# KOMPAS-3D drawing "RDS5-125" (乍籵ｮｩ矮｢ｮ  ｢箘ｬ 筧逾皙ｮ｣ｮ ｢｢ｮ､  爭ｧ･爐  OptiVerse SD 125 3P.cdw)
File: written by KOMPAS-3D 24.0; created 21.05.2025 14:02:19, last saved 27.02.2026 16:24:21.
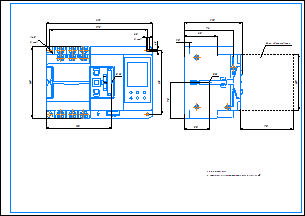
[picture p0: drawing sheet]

Document properties: Утвердил: Строгонов; Автор: keaz-admin; Проверил: Дорошев; Форматы листов документа: A2; Полное имя файла: D:\Проекты\OptiVerse SD\OptiVerse SD\OptiVerse SD 125 3P\КД\ГЖИК.648446.002ГЧ Устройство автоматического ввода резерва OptiVerse SD 125 3P (без рамки).cdw; Масса: 3.4; Т. контр.: Пашков А.Е.; Наименование: Устройство автоматического ввода резерва OptiVerse SD 125 3P / Габаритный чертеж; Н. контр.: Гаврикова; Количество листов документа: 1; Разработал: Сулейманова

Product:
- Body: Тело 4
    Масса: 0.000009
- Body: Тело 3
    Масса: 0.000001
- Component [assembly]: RDS5-125.STEP  | qty 1  | pos. 1  | Масса: 15.228655; source file: ..\3D\Сборка OptiVerse SD 125 3P.a3d
- Body: Тело 2
    Масса: 0.000056
- Part/product: RDS5-125
    Масса: 15.22872
    Форматы листов документа: A2

Views: Проекционный вид 2
Referenced files in D:\Проекты\OptiVerse SD\OptiVerse SD\OptiVerse SD 125 3P\КД\: ГЖИК.648446.002СБ Устройство автоматического ввода резерва OptiVerse SD 125 3P.cdw
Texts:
  Зона обслуживания
  Устройство автоматического
  ввода резерва OptiVerse SD 125 3P
  Габаритный чертеж
  ГЖИК.648446.002ГЧ
  Сулейманова
  Дорошев
  ГЖИК.648446.002
  Гаврикова
  Строгонов
  АО "КЭАЗ"
  Пашков А.Е.
  Без основной надписи.
Dimensions and other numbers on the sheet: 115; 96; 10; 65; 70; 50; 90; 109; 1:1; 0; 1; 2; 3,4

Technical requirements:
  Ц.М. - центр масс.
  Отклонение координат от центра масс не более 10 %.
